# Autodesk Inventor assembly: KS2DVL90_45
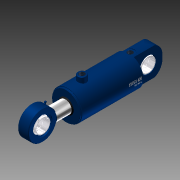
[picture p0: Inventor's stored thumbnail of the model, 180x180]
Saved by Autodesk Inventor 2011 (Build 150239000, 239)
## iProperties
Created: 2010-10
Document SubType Name: Assembly
Designer: TB
Mass: 566.294 g
Surface Area: 1153.75 cm^2
Volume: 566.294 cm^3
Density: 1 g/cm^3
Description: KS2DVL 90/45 - 100 mm
Slaglengde: 100,000 mm
Author: TB
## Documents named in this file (6)
- C:\Vault\Sylinderteknikk\Projects_ST\3D.nettkatalog\KS2-Series\KS2DVL\KS2DVL90_45\KS2DVL90_45.iam
- C:\Vault\Sylinderteknikk\Projects_ST\3D.nettkatalog\KS2-Series\KS2DVL\KS2DVL90_45\KS2DVL90_45_stang.ipt
- C:\Vault\Sylinderteknikk\Projects_ST\3D.nettkatalog\KS2-Series\KS2DVL\KS2DVL90_45\KS2DVL90_45_Parameters.ipt
- C:\Vault\Sylinderteknikk\Projects_ST\3D.nettkatalog\KS2-Series\KS2DVL\KS2DVL90_45\KS2DVL90_45_body..ipt
- C:\Vault\Sylinderteknikk\Imported Components\27-7785-03\Part40.ipt
- C:\Vault\Sylinderteknikk\Projects_ST\Øyer\Klinkby.KS.Øyer\KS.45.eye.komplett\KS.45.Eye.Komplett.ipt
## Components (5 placed, 5 different names)
1. KS2DVL90_45_Parameters:3
2. KS2DVL90_45_stang:1 — Mate:1, FriMate:2, Mate:3, Insert:3
3. KS2DVL90_45_body.:1 — Mate:1, FriMate:2, Mate:3, Insert:2, Angle:1
4. Part40:1 — Insert:2
5. KS.45.Eye.Komplett:1 — Insert:3, Angle:1
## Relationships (6: Mate 3, Insert 2, Angle 1)
- Mate:1: KS2DVL90_45_stang:1 ↔ KS2DVL90_45_body.:1
- FriMate:2 [Mate]: KS2DVL90_45_stang:1 ↔ KS2DVL90_45_body.:1
- Mate:3: KS2DVL90_45_stang:1 ↔ KS2DVL90_45_body.:1
- Insert:2: KS2DVL90_45_body.:1 ↔ Part40:1
- Insert:3: KS2DVL90_45_stang:1 ↔ KS.45.Eye.Komplett:1
- Angle:1: KS2DVL90_45_body.:1 ↔ KS.45.Eye.Komplett:1
## Named parameters: Forlengelse_rør = 0, Vinkel_Minusport = 0
